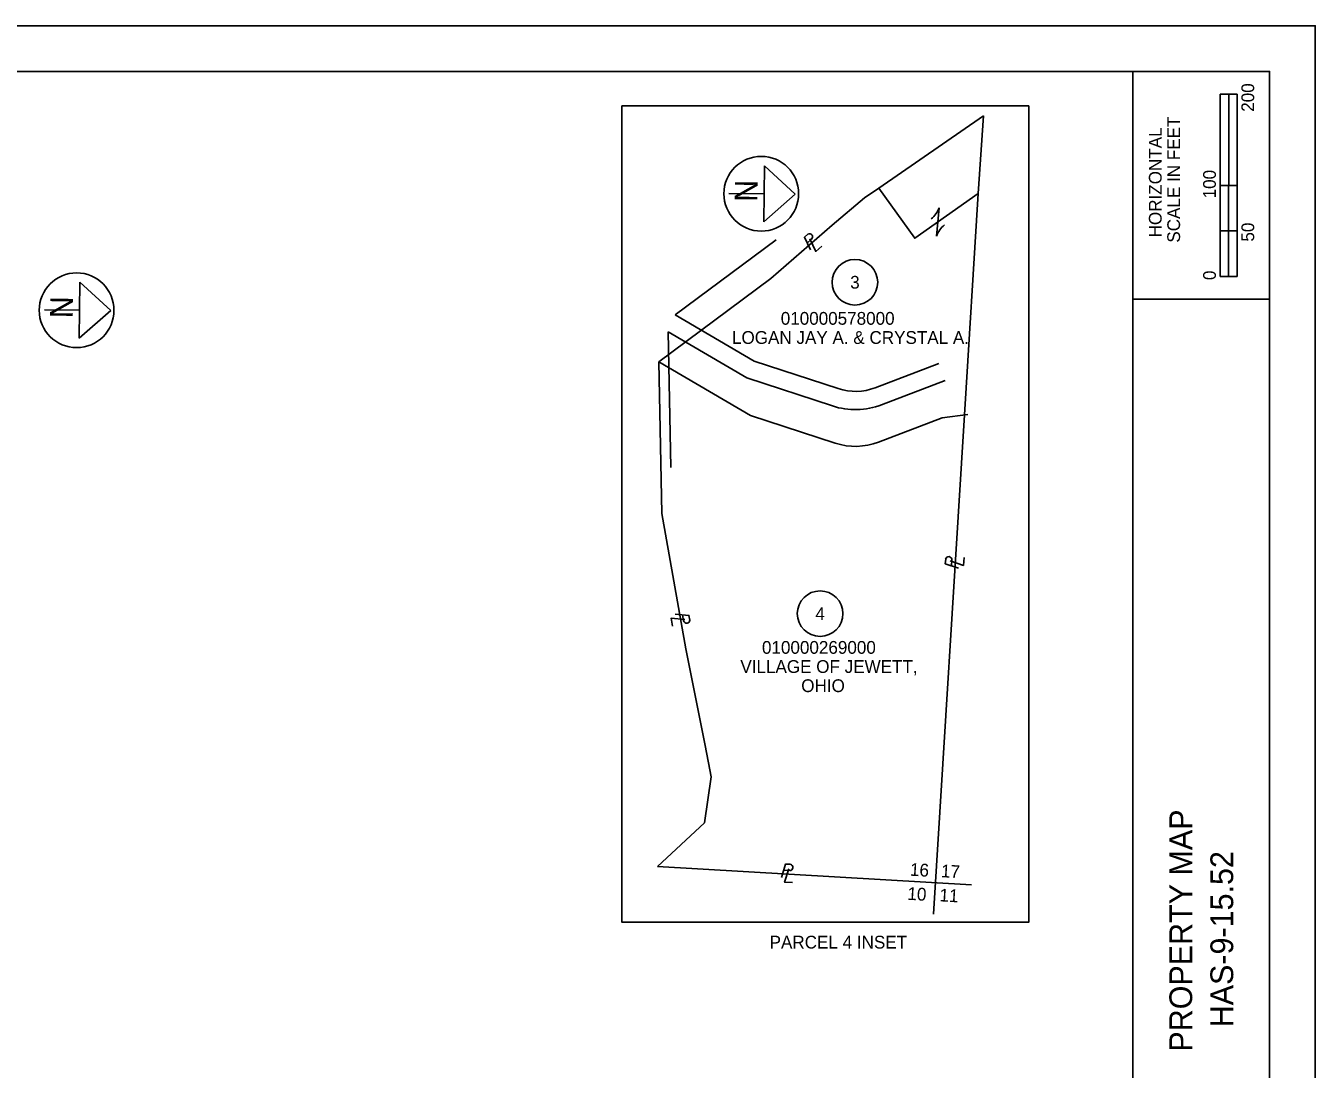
# Model space of a CAD drawing. Extents: x -2.6 to 34, y 0 to 22.
# Drawn here: x 19.85 to 34, y 10.56 to 22 of the extents above; entities that cross this region are included whole.
import ezdxf

# ---------------------------------------------------------------- set-up
doc = ezdxf.new("R2010")
doc.units = 0
for name, color, linetype in [('Default', 7, 'Continuous'), ('RW_P_Esmt_SC', 7, 'Continuous'), ('RW_X_CL', 7, 'Continuous'), ('SH_Border', 7, 'Continuous'), ('SH_Cut_Line', 7, 'Continuous'), ('SH_Data', 7, 'Continuous'), ('SH_Masking', 7, 'Continuous')]:
    doc.layers.add(name, color=color, linetype=linetype)

msp = doc.modelspace()

# ---------------------------------------------------------------- linework, layer by layer
at = {"layer": 'Default'}
for centre in [(28.949, 19.187), (28.567, 15.552)]:
    msp.add_circle(centre, 0.25, dxfattribs=at)
at = {"layer": 'RW_P_Esmt_SC'}
for p, q in [((28.085, 19.652), (26.977, 18.828)), ((26.977, 18.828), (27.845, 18.321)), ((26.9, 18.642), (26.93, 17.154)), ((26.9, 18.642), (27.762, 18.138)), ((27.845, 18.321), (28.765, 18.02)), ((29.171, 18.03), (29.87, 18.297)), ((27.762, 18.138), (28.703, 17.83)), ((29.242, 17.843), (29.941, 18.11))]:
    msp.add_line(p, q, dxfattribs=at)
for radius in [0.607, 0.807]:
    msp.add_arc((28.954, 18.597), radius, 251.8657, 290.9277, dxfattribs=at)
at = {"layer": 'RW_X_CL'}
for p, q in [((29.054, 20.114), (28.701, 19.815)), ((29.212, 20.22), (29.054, 20.114)), ((28.701, 19.815), (28.025, 19.229)), ((28.025, 19.229), (26.796, 18.316)), ((26.796, 18.316), (26.83, 16.649)), ((26.796, 18.316), (27.803, 17.727)), ((27.803, 17.727), (28.734, 17.422)), ((29.207, 17.434), (29.906, 17.701)), ((29.906, 17.701), (30.189, 17.737)), ((26.83, 16.649), (27.092, 15.166)), ((27.092, 15.166), (27.305, 14.106)), ((27.305, 14.106), (27.358, 13.839)), ((27.373, 13.763), (27.298, 13.256)), ((27.358, 13.839), (27.373, 13.763)), ((27.298, 13.256), (26.781, 12.778))]:
    msp.add_line(p, q, dxfattribs=at)
msp.add_arc((28.954, 18.094), 0.707, 251.8657, 290.9277, dxfattribs=at)
at = {"layer": 'SH_Border'}
for p, q in [((32, 0.5), (32, 21.5)), ((32, 19), (33.5, 19))]:
    msp.add_line(p, q, dxfattribs=at)
msp.add_lwpolyline([(1.5, 21.5), (33.5, 21.5), (33.5, 0.5), (1.5, 0.5)], close=True, dxfattribs=at)
for centre in [(27.921, 20.158), (20.408, 18.88)]:
    msp.add_circle(centre, 0.41, dxfattribs=at)
at = {"layer": 'SH_Cut_Line'}
msp.add_lwpolyline([(0, 0), (34, 0), (34, 22), (0, 22)], close=True, dxfattribs=at)
at = {"layer": 'SH_Data'}
for p, q in [((32.957, 19.25), (32.957, 21.25)), ((33.144, 21.25), (32.957, 21.25)), ((32.957, 20.25), (32.957, 21.25)), ((32.957, 21.25), (33.05, 21.25)), ((33.05, 21.25), (33.051, 21.25)), ((33.051, 21.25), (33.051, 20.25)), ((33.144, 21.25), (33.144, 19.25)), ((27.957, 20.465), (27.95, 19.85)), ((28.295, 20.153), (27.957, 20.465)), ((33.051, 20.25), (32.957, 20.25)), ((33.143, 20.25), (33.05, 20.25)), ((33.05, 20.25), (33.05, 19.75)), ((33.143, 19.75), (33.143, 20.25)), ((27.954, 20.157), (27.567, 20.162)), ((27.95, 19.85), (28.295, 20.153)), ((33.05, 19.75), (32.957, 19.75)), ((32.957, 19.75), (32.957, 19.25)), ((33.05, 19.25), (33.05, 19.75)), ((33.05, 19.75), (33.143, 19.75)), ((28.424, 19.617), (28.474, 19.659)), ((28.475, 19.619), (28.475, 19.619)), ((33.144, 19.25), (32.957, 19.25)), ((32.957, 19.25), (33.05, 19.25)), ((20.445, 19.187), (20.437, 18.572)), ((20.782, 18.876), (20.445, 19.187)), ((20.441, 18.88), (20.054, 18.884)), ((20.437, 18.572), (20.782, 18.876)), ((30.009, 16.076), (30.013, 16.141)), ((30.042, 16.115), (30.042, 16.115)), ((27.034, 15.493), (27.034, 15.493)), ((27.057, 15.538), (27.069, 15.475)), ((28.168, 12.737), (28.233, 12.735)), ((28.207, 12.704), (28.207, 12.704))]:
    msp.add_line(p, q, dxfattribs=at)
msp.add_lwpolyline([(26.392, 21.122), (30.857, 21.122), (30.857, 12.168), (26.392, 12.168)], close=True, dxfattribs=at)
for points in [[(28.46, 19.543), (28.394, 19.681), (28.433, 19.714)], [(28.454, 19.664), (28.519, 19.526), (28.586, 19.582)], [(30.087, 16.051), (29.941, 16.099), (29.945, 16.15)], [(29.995, 16.131), (30.14, 16.082), (30.146, 16.169)], [(27.083, 15.489), (26.931, 15.501), (26.947, 15.415)], [(26.975, 15.545), (27.128, 15.533), (27.137, 15.482)], [(28.144, 12.658), (28.188, 12.805), (28.24, 12.803)], [(28.222, 12.752), (28.177, 12.606), (28.264, 12.602)]]:
    msp.add_lwpolyline(points, dxfattribs=at)
for centre in [(27.921, 20.158), (20.408, 18.88)]:
    msp.add_circle(centre, 0.41, dxfattribs=at)
for centre, start, end in [((28.451, 19.685), 310.6491, 121.5062), ((29.978, 16.143), 356.8843, 167.7414), ((27.103, 15.481), 190.833, 1.6901), ((28.234, 12.769), 268.2904, 79.1475)]:
    msp.add_arc(centre, 0.0345, start, end, dxfattribs=at)
at = {"layer": 'SH_Masking'}
for p, q in [((29.212, 20.22), (30.361, 21.013)), ((30.302, 20.16), (30.361, 21.013)), ((29.846, 19.693), (29.872, 20.005)), ((29.859, 19.849), (29.859, 19.849)), ((30.151, 17.732), (29.812, 12.256)), ((30.228, 12.578), (26.781, 12.778))]:
    msp.add_line(p, q, dxfattribs=at)
msp.add_lwpolyline([(29.212, 20.22), (29.605, 19.67), (30.302, 20.16), (30.151, 17.732)], dxfattribs=at)
for centre, start, end in [((29.619, 20.09), 308.7577, 341.4002), ((30.099, 19.608), 128.7577, 161.4002)]:
    msp.add_arc(centre, 0.267, start, end, dxfattribs=at)

# ---------------------------------------------------------------- texts
at = {"layer": 'Default'}
for s, p in [('3', (28.897, 19.117)), ('010000578000', (28.135, 18.721)), ('LOGAN JAY A. & CRYSTAL A.', (27.6, 18.511)), ('4', (28.515, 15.482)), ('010000269000', (27.929, 15.112)), ('VILLAGE OF JEWETT,', (27.692, 14.902)), ('OHIO', (28.36, 14.692))]:
    msp.add_text(s, height=0.14, dxfattribs=at).set_placement(p)
for s, p in [('16', (29.55, 12.678)), ('17', (29.89, 12.662)), ('10', (29.522, 12.414)), ('11', (29.874, 12.397))]:
    msp.add_text(s, height=0.14, rotation=356.6822, dxfattribs=at).set_placement(p)
at = {"layer": 'SH_Data'}
for s, height, rotation, p in [('200', 0.14, 90, (33.33, 21.057)), ('SCALE IN FEET', 0.14, 90, (32.517, 19.621)), ('HORIZONTAL', 0.14, 90, (32.315, 19.679)), ('100', 0.14, 90, (32.91, 20.107)), ('N', 0.25, 269.3245, (27.632, 20.312)), ('50', 0.14, 90, (33.33, 19.633)), ('0', 0.14, 90, (32.91, 19.211)), ('N', 0.25, 269.3245, (20.119, 19.035)), ('PROPERTY MAP', 0.25, 90, (32.65, 10.748)), ('HAS-9-15.52', 0.25, 90, (33.1, 11.015))]:
    msp.add_text(s, height=height, rotation=rotation, dxfattribs=at).set_placement(p)
msp.add_text('PARCEL 4 INSET', height=0.14, dxfattribs=at).set_placement((28.013, 11.879))

doc.saveas('drawing.dxf')
